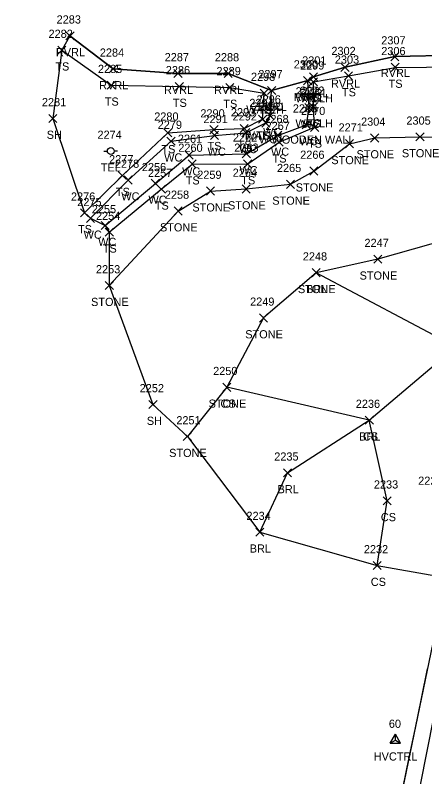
# Model space of a CAD drawing. Extents: x 1472022 to 1479249, y 777216 to 786527.
# Drawn here: x 1473450.2 to 1473550.5, y 779278.4 to 779464.9 of the extents above; entities that cross this region are included whole.
import ezdxf

# ---------------------------------------------------------------- set-up
doc = ezdxf.new("R2010")
doc.units = 0
for name, color, linetype in [('C_A', 7, 'Continuous'), ('C_I', 7, 'Continuous'), ('CPSM', 7, 'Continuous'), ('D_A', 7, 'Continuous'), ('D_C', 7, 'Continuous'), ('D_I', 7, 'Continuous'), ('D_TIC', 7, 'Continuous'), ('DHW', 7, 'Continuous'), ('L_A', 7, 'Continuous'), ('L_I', 7, 'Continuous'), ('L_TIC', 7, 'Continuous'), ('LABL', 7, 'Continuous'), ('LASF', 7, 'Continuous'), ('LAWE', 7, 'Continuous'), ('LELB', 7, 'Continuous'), ('LSOGP', 7, 'Continuous'), ('PET', 7, 'Continuous'), ('PSP', 7, 'Continuous'), ('U_A', 7, 'Continuous'), ('U_I', 7, 'Continuous'), ('UP', 7, 'Continuous')]:
    doc.layers.add(name, color=color, linetype=linetype)

msp = doc.modelspace()

# ---------------------------------------------------------------- linework, layer by layer
at = {"layer": 'CPSM'}
for p, q in [((1473542.08, 779286.66), (1473543.33, 779288.82)), ((1473544.58, 779286.66), (1473543.33, 779288.82)), ((1473543.33, 779287.38), (1473543.33, 779288.82)), ((1473542.08, 779286.66), (1473543.33, 779287.38)), ((1473542.08, 779286.66), (1473544.58, 779286.66)), ((1473543.33, 779287.38), (1473543.33, 779287.38)), ((1473543.33, 779287.38), (1473544.58, 779286.66))]:
    msp.add_line(p, q, dxfattribs=at)
at = {"layer": 'D_TIC'}
for points in [[(1473522.26, 779447.59), (1473524.26, 779449.59)], [(1473524.26, 779447.59), (1473522.26, 779449.59)], [(1473510.22, 779444.82), (1473512.22, 779446.82)], [(1473512.22, 779444.82), (1473510.22, 779446.82)], [(1473522.26, 779441.43), (1473524.26, 779443.43)], [(1473524.26, 779441.43), (1473522.26, 779443.43)], [(1473509.83, 779438.42), (1473511.83, 779440.42)], [(1473511.83, 779438.42), (1473509.83, 779440.42)]]:
    msp.add_lwpolyline(points, dxfattribs=at)
at = {"layer": 'DHW'}
for points in [[(1473523.26, 779442.43), (1473523.26, 779448.59)], [(1473510.83, 779439.42), (1473511.22, 779445.82)]]:
    msp.add_lwpolyline(points, dxfattribs=at)
at = {"layer": 'L_TIC'}
for points in [[(1473462.64, 779458.86), (1473464.64, 779460.86)], [(1473464.64, 779458.86), (1473462.64, 779460.86)], [(1473460.66, 779455.35), (1473462.66, 779457.35)], [(1473462.66, 779455.35), (1473460.66, 779457.35)], [(1473542.2, 779453.75), (1473544.2, 779455.75)], [(1473544.2, 779453.75), (1473542.2, 779455.75)], [(1473473.22, 779450.75), (1473475.22, 779452.75)], [(1473475.22, 779450.75), (1473473.22, 779452.75)], [(1473530, 779451.15), (1473532, 779453.15)], [(1473532, 779451.15), (1473530, 779453.15)], [(1473542.26, 779451.12), (1473544.26, 779453.12)], [(1473544.26, 779451.12), (1473542.26, 779453.12)], [(1473489.1, 779449.63), (1473491.1, 779451.63)], [(1473491.1, 779449.63), (1473489.1, 779451.63)], [(1473501.38, 779449.61), (1473503.38, 779451.61)], [(1473503.38, 779449.61), (1473501.38, 779451.61)], [(1473522.28, 779448.82), (1473524.28, 779450.82)], [(1473524.28, 779448.82), (1473522.28, 779450.82)], [(1473530.84, 779449.04), (1473532.84, 779451.04)], [(1473532.84, 779449.04), (1473530.84, 779451.04)], [(1473472.76, 779446.75), (1473474.76, 779448.75)], [(1473474.76, 779446.75), (1473472.76, 779448.75)], [(1473489.43, 779446.45), (1473491.43, 779448.45)], [(1473491.43, 779446.45), (1473489.43, 779448.45)], [(1473501.79, 779446.21), (1473503.79, 779448.21)], [(1473503.79, 779446.21), (1473501.79, 779448.21)], [(1473520.87, 779447.87), (1473522.87, 779449.87)], [(1473522.87, 779447.87), (1473520.87, 779449.87)], [(1473520.87, 779447.87), (1473522.87, 779449.87)], [(1473522.87, 779447.87), (1473520.87, 779449.87)], [(1473522.26, 779447.59), (1473524.26, 779449.59)], [(1473524.26, 779447.59), (1473522.26, 779449.59)], [(1473510.22, 779444.82), (1473512.22, 779446.82)], [(1473512.22, 779444.82), (1473510.22, 779446.82)], [(1473512.03, 779445.48), (1473514.03, 779447.48)], [(1473514.03, 779445.48), (1473512.03, 779447.48)], [(1473512.03, 779445.48), (1473514.03, 779447.48)], [(1473514.03, 779445.48), (1473512.03, 779447.48)], [(1473521.18, 779441.26), (1473523.18, 779443.26)], [(1473523.18, 779441.26), (1473521.18, 779443.26)], [(1473522.26, 779441.43), (1473524.26, 779443.43)], [(1473524.26, 779441.43), (1473522.26, 779443.43)], [(1473458.47, 779438.62), (1473460.47, 779440.62)], [(1473460.47, 779438.62), (1473458.47, 779440.62)], [(1473511.65, 779439.29), (1473513.65, 779441.29)], [(1473513.65, 779439.29), (1473511.65, 779441.29)], [(1473509.83, 779438.42), (1473511.83, 779440.42)], [(1473511.83, 779438.42), (1473509.83, 779440.42)], [(1473510.6, 779437.51), (1473512.6, 779439.51)], [(1473512.6, 779437.51), (1473510.6, 779439.51)], [(1473520.53, 779437.07), (1473522.53, 779439.07)], [(1473522.53, 779437.07), (1473520.53, 779439.07)], [(1473486.63, 779435.09), (1473488.63, 779437.09)], [(1473488.63, 779435.09), (1473486.63, 779437.09)], [(1473497.92, 779435.87), (1473499.92, 779437.87)], [(1473499.92, 779435.87), (1473497.92, 779437.87)], [(1473505.31, 779436.14), (1473507.31, 779438.14)], [(1473507.31, 779436.14), (1473505.31, 779438.14)], [(1473505.73, 779435.12), (1473507.73, 779437.12)], [(1473507.73, 779435.12), (1473505.73, 779437.12)], [(1473522.55, 779436.45), (1473524.55, 779438.45)], [(1473524.55, 779436.45), (1473522.55, 779438.45)], [(1473487.4, 779433.07), (1473489.4, 779435.07)], [(1473489.4, 779433.07), (1473487.4, 779435.07)], [(1473498.04, 779434.48), (1473500.04, 779436.48)], [(1473500.04, 779434.48), (1473498.04, 779436.48)], [(1473513.56, 779434.48), (1473515.56, 779436.48)], [(1473515.56, 779434.48), (1473513.56, 779436.48)], [(1473537.27, 779433.84), (1473539.27, 779435.84)], [(1473539.27, 779433.84), (1473537.27, 779435.84)], [(1473548.37, 779434.1), (1473550.37, 779436.1)], [(1473550.37, 779434.1), (1473548.37, 779436.1)], [(1473513.85, 779432.81), (1473515.85, 779434.81)], [(1473515.85, 779432.81), (1473513.85, 779434.81)], [(1473531.1, 779432.42), (1473533.1, 779434.42)], [(1473533.1, 779432.42), (1473531.1, 779434.42)], [(1473491.8, 779429.65), (1473493.8, 779431.65)], [(1473493.8, 779429.65), (1473491.8, 779431.65)], [(1473505.84, 779429.95), (1473507.84, 779431.95)], [(1473507.84, 779429.95), (1473505.84, 779431.95)], [(1473492.58, 779427.45), (1473494.58, 779429.45)], [(1473494.58, 779427.45), (1473492.58, 779429.45)], [(1473506.18, 779427.47), (1473508.18, 779429.47)], [(1473508.18, 779427.47), (1473506.18, 779429.47)], [(1473522.38, 779425.73), (1473524.38, 779427.73)], [(1473524.38, 779425.73), (1473522.38, 779427.73)], [(1473475.49, 779424.63), (1473477.49, 779426.63)], [(1473477.49, 779424.63), (1473475.49, 779426.63)], [(1473476.91, 779423.53), (1473478.91, 779425.53)], [(1473478.91, 779423.53), (1473476.91, 779425.53)], [(1473483.57, 779422.71), (1473485.57, 779424.71)], [(1473485.57, 779422.71), (1473483.57, 779424.71)], [(1473516.64, 779422.49), (1473518.64, 779424.49)], [(1473518.64, 779422.49), (1473516.64, 779424.49)], [(1473485.01, 779421.29), (1473487.01, 779423.29)], [(1473487.01, 779421.29), (1473485.01, 779423.29)], [(1473497.08, 779420.83), (1473499.08, 779422.83)], [(1473499.08, 779420.83), (1473497.08, 779422.83)], [(1473505.81, 779421.34), (1473507.81, 779423.34)], [(1473507.81, 779421.34), (1473505.81, 779423.34)], [(1473466.21, 779415.5), (1473468.21, 779417.5)], [(1473468.21, 779415.5), (1473466.21, 779417.5)], [(1473489.14, 779415.95), (1473491.14, 779417.95)], [(1473491.14, 779415.95), (1473489.14, 779417.95)], [(1473467.69, 779414.16), (1473469.69, 779416.16)], [(1473469.69, 779414.16), (1473467.69, 779416.16)], [(1473471.25, 779412.4), (1473473.25, 779414.4)], [(1473473.25, 779412.4), (1473471.25, 779414.4)], [(1473472.28, 779410.76), (1473474.28, 779412.76)], [(1473474.28, 779410.76), (1473472.28, 779412.76)], [(1473538.02, 779404.15), (1473540.02, 779406.15)], [(1473540.02, 779404.15), (1473538.02, 779406.15)], [(1473522.92, 779400.84), (1473524.92, 779402.84)], [(1473524.92, 779400.84), (1473522.92, 779402.84)], [(1473522.92, 779400.84), (1473524.92, 779402.84)], [(1473524.92, 779400.84), (1473522.92, 779402.84)], [(1473472.27, 779397.69), (1473474.27, 779399.69)], [(1473474.27, 779397.69), (1473472.27, 779399.69)], [(1473510.03, 779389.76), (1473512.03, 779391.76)], [(1473512.03, 779389.76), (1473510.03, 779391.76)], [(1473501.06, 779372.78), (1473503.06, 779374.78)], [(1473503.06, 779372.78), (1473501.06, 779374.78)], [(1473501.06, 779372.78), (1473503.06, 779374.78)], [(1473503.06, 779372.78), (1473501.06, 779374.78)], [(1473482.98, 779368.57), (1473484.98, 779370.57)], [(1473484.98, 779368.57), (1473482.98, 779370.57)], [(1473535.94, 779364.74), (1473537.94, 779366.74)], [(1473537.94, 779364.74), (1473535.94, 779366.74)], [(1473535.94, 779364.74), (1473537.94, 779366.74)], [(1473537.94, 779364.74), (1473535.94, 779366.74)], [(1473491.39, 779360.71), (1473493.39, 779362.71)], [(1473493.39, 779360.71), (1473491.39, 779362.71)], [(1473515.93, 779351.83), (1473517.93, 779353.83)], [(1473517.93, 779351.83), (1473515.93, 779353.83)], [(1473540.33, 779344.99), (1473542.33, 779346.99)], [(1473542.33, 779344.99), (1473540.33, 779346.99)], [(1473509.12, 779337.3), (1473511.12, 779339.3)], [(1473511.12, 779337.3), (1473509.12, 779339.3)], [(1473537.87, 779329.14), (1473539.87, 779331.14)], [(1473539.87, 779329.14), (1473537.87, 779331.14)]]:
    msp.add_lwpolyline(points, dxfattribs=at)
at = {"layer": 'LABL'}
msp.add_lwpolyline([(1473510.12, 779338.3), (1473516.93, 779352.83), (1473536.94, 779365.74), (1473558.14, 779383.69), (1473523.92, 779401.84)], dxfattribs=at)
at = {"layer": 'LASF'}
for points in [[(1473473.27, 779398.69), (1473490.14, 779416.95), (1473498.08, 779421.83), (1473506.81, 779422.34), (1473517.64, 779423.49), (1473523.38, 779426.73), (1473532.1, 779433.42), (1473538.27, 779434.84), (1473549.37, 779435.1), (1473559.65, 779434.83), (1473570.73, 779429.96), (1473585.71, 779426.72), (1473606.62, 779429.3), (1473628.1, 779421.5), (1473649.11, 779417.23), (1473669, 779413.11), (1473690.95, 779410.4), (1473712.68, 779400.49)], [(1473633.09, 779342.06), (1473637.36, 779354.76), (1473634.83, 779370.15), (1473634.39, 779386.13), (1473619.75, 779393.9), (1473604.91, 779393.47), (1473602.82, 779381.23), (1473597.4, 779362.46), (1473593.63, 779347.94), (1473579.62, 779350.93), (1473559.31, 779355.6), (1473561.08, 779365.73), (1473563.08, 779383.25), (1473565.84, 779398.86), (1473566.45, 779410.85), (1473556.37, 779410.02), (1473539.02, 779405.15), (1473523.92, 779401.84), (1473511.03, 779390.76), (1473502.06, 779373.78), (1473492.39, 779361.71)]]:
    msp.add_lwpolyline(points, dxfattribs=at)
at = {"layer": 'LAWE'}
for points in [[(1473463.64, 779459.86), (1473474.22, 779451.75), (1473490.1, 779450.63), (1473502.38, 779450.61), (1473513.03, 779446.48), (1473521.87, 779448.87), (1473523.28, 779449.82), (1473531, 779452.15), (1473543.2, 779454.75), (1473558.32, 779455.14), (1473569.13, 779457.8), (1473574.75, 779460.53), (1473588.89, 779462.56)], [(1473472.25, 779413.4), (1473484.57, 779423.71), (1473492.8, 779430.65), (1473506.84, 779430.95), (1473514.56, 779435.48), (1473521.53, 779438.07), (1473522.18, 779442.26), (1473521.87, 779448.87)], [(1473468.69, 779415.16), (1473477.91, 779424.53), (1473488.4, 779434.07), (1473499.04, 779435.48), (1473506.73, 779436.12), (1473511.6, 779438.51), (1473512.65, 779440.29), (1473513.03, 779446.48)]]:
    msp.add_lwpolyline(points, dxfattribs=at)
at = {"layer": 'LELB'}
for points in [[(1473523.26, 779448.59), (1473531.84, 779450.04), (1473543.26, 779452.12), (1473558.64, 779452.25), (1473569.37, 779453.99), (1473575.52, 779457.41), (1473586.54, 779458.61), (1473591.28, 779462.14)], [(1473461.66, 779456.35), (1473473.76, 779447.75), (1473490.43, 779447.45), (1473502.79, 779447.21), (1473511.22, 779445.82)], [(1473473.28, 779411.76), (1473486.01, 779422.29), (1473493.58, 779428.45), (1473507.18, 779428.47), (1473514.85, 779433.81), (1473523.55, 779437.45), (1473523.26, 779442.43)], [(1473467.21, 779416.5), (1473476.49, 779425.63), (1473487.63, 779436.09), (1473498.92, 779436.87), (1473506.31, 779437.14), (1473510.83, 779439.42)], [(1473538.87, 779330.14), (1473541.33, 779345.99), (1473536.94, 779365.74), (1473502.06, 779373.78)]]:
    msp.add_lwpolyline(points, dxfattribs=at)
at = {"layer": 'LSOGP'}
for points in [[(1473558.32, 779455.14), (1473543.2, 779454.75), (1473531, 779452.15), (1473523.28, 779449.82), (1473521.87, 779448.87), (1473513.03, 779446.48), (1473502.38, 779450.61), (1473490.1, 779450.63), (1473474.22, 779451.75), (1473463.64, 779459.86), (1473461.66, 779456.35), (1473459.47, 779439.62), (1473467.21, 779416.5), (1473468.69, 779415.16), (1473472.25, 779413.4), (1473473.28, 779411.76), (1473473.27, 779398.69), (1473483.98, 779369.57), (1473492.39, 779361.71), (1473510.12, 779338.3), (1473538.87, 779330.14), (1473553.21, 779327.61)], [(1473551.15, 779304.84), (1473549.65, 779297.61), (1473548.15, 779290.38), (1473546.65, 779283.15), (1473545.15, 779275.93)]]:
    msp.add_lwpolyline(points, dxfattribs=at)
at = {"layer": 'PET'}
msp.add_lwpolyline([(1473559.55, 779345.54), (1473562.13, 779344.85), (1473559.08, 779325.48), (1473547.78, 779268.19), (1473538.56, 779219.47), (1473529.75, 779172.07), (1473520.23, 779121.16), (1473510.25, 779071.91), (1473501.42, 779032.79), (1473487.97, 778980.7), (1473476.59, 778937.83), (1473460.83, 778885.95), (1473443.7, 778834.83), (1473427.04, 778789.1), (1473404.79, 778732.7), (1473383.99, 778685.53), (1473360.34, 778636.02), (1473337.25, 778590.82), (1473309.69, 778539.48), (1473284.14, 778496.13), (1473255.52, 778449.63), (1473221.14, 778399.57)], dxfattribs=at)
at = {"layer": 'PSP'}
msp.add_lwpolyline([(1473559.55, 779345.54), (1473556.55, 779328.39), (1473555.66, 779326.52), (1473543.65, 779268.7), (1473533.24, 779220.88), (1473523.59, 779172.64), (1473513.3, 779122.79), (1473502.95, 779073.62), (1473494.24, 779034.96), (1473482.21, 778985.43), (1473469.56, 778939.68), (1473453.46, 778887.37), (1473437.09, 778838.65), (1473419.76, 778792.02), (1473397.52, 778736.13), (1473377.14, 778688.43), (1473353.45, 778638.67), (1473330.09, 778593.76), (1473303, 778543.94), (1473277.25, 778499.77), (1473248.4, 778453.47), (1473214.72, 778403.13)], dxfattribs=at)
at = {"layer": 'UP'}
for p, q in [((1473471.98, 779431.62), (1473472.81, 779431.62)), ((1473473.64, 779431.63), (1473473.64, 779431.63)), ((1473475.31, 779431.63), (1473474.47, 779431.63)), ((1473474.47, 779431.63), (1473474.47, 779431.63)), ((1473475.31, 779431.63), (1473475.31, 779431.63))]:
    msp.add_line(p, q, dxfattribs=at)
msp.add_circle((1473473.64, 779431.63), 0.833, dxfattribs=at)

# ---------------------------------------------------------------- texts
at = {"layer": 'C_A'}
msp.add_text('HVCTRL', height=2, dxfattribs=at).set_placement((1473538.03, 779282.38))
at = {"layer": 'C_I'}
msp.add_text('60', height=2, dxfattribs=at).set_placement((1473541.73, 779290.38))
at = {"layer": 'D_A'}
for p in [(1473518.85, 779443.59), (1473506.81, 779440.82), (1473518.85, 779437.43), (1473506.42, 779434.42)]:
    msp.add_text('WALLH', height=2, dxfattribs=at).set_placement(p)
at = {"layer": 'D_C'}
msp.add_text('WOODEN WALL', height=2, dxfattribs=at).set_placement((1473513, 779433.43))
at = {"layer": 'D_I'}
for s, p in [('2299', (1473519.99, 779451.59)), ('2298', (1473507.96, 779448.82)), ('2272', (1473520, 779445.43)), ('2294', (1473507.57, 779442.42))]:
    msp.add_text(s, height=2, dxfattribs=at).set_placement(p)
at = {"layer": 'L_A'}
for s, p in [('RVRL', (1473460.21, 779454.86)), ('TS', (1473460.07, 779451.35)), ('RVRL', (1473539.77, 779449.75)), ('RVRL', (1473470.79, 779446.75)), ('RVRL', (1473527.56, 779447.15)), ('TS', (1473541.67, 779447.12)), ('RVRL', (1473486.66, 779445.63)), ('RVRL', (1473498.95, 779445.61)), ('RVRL', (1473519.84, 779444.82)), ('TS', (1473530.25, 779445.04)), ('TS', (1473472.17, 779442.75)), ('TS', (1473488.84, 779442.45)), ('RVRL', (1473518.44, 779443.87)), ('WC', (1473520.18, 779443.87)), ('TS', (1473521.67, 779443.59)), ('TS', (1473501.2, 779442.21)), ('TS', (1473509.63, 779440.82)), ('RVRL', (1473509.6, 779441.48)), ('WC', (1473511.34, 779441.48)), ('WC', (1473520.48, 779437.26)), ('TS', (1473521.67, 779437.43)), ('WC', (1473510.96, 779435.29)), ('SH', (1473457.96, 779434.62)), ('TS', (1473509.24, 779434.42)), ('WC', (1473509.91, 779433.51)), ('WC', (1473519.84, 779433.07)), ('TS', (1473486.04, 779431.09)), ('TS', (1473497.33, 779431.87)), ('TS', (1473504.71, 779432.14)), ('WC', (1473505.03, 779431.12)), ('TS', (1473521.96, 779432.45)), ('WC', (1473497.34, 779430.48)), ('WC', (1473512.86, 779430.48)), ('STONE', (1473533.81, 779429.84)), ('STONE', (1473544.92, 779430.1)), ('WC', (1473486.71, 779429.07)), ('TS', (1473513.26, 779428.81)), ('STONE', (1473527.64, 779428.42)), ('WC', (1473491.11, 779425.65)), ('WC', (1473505.15, 779425.95)), ('TS', (1473491.99, 779423.45)), ('TS', (1473505.59, 779423.47)), ('TS', (1473474.9, 779420.63)), ('STONE', (1473518.93, 779421.73)), ('WC', (1473476.22, 779419.53)), ('WC', (1473482.87, 779418.71)), ('STONE', (1473513.18, 779418.49)), ('TS', (1473484.42, 779417.29)), ('STONE', (1473493.62, 779416.83)), ('STONE', (1473502.35, 779417.34)), ('TS', (1473465.62, 779411.5)), ('STONE', (1473485.68, 779411.95)), ('WC', (1473466.99, 779410.16)), ('WC', (1473470.55, 779408.4)), ('TS', (1473471.68, 779406.76)), ('STONE', (1473534.57, 779400.15)), ('STONE', (1473519.47, 779396.84)), ('BRL', (1473521.47, 779396.84)), ('STONE', (1473468.81, 779393.69)), ('STONE', (1473506.57, 779385.76)), ('STONE', (1473497.6, 779368.78)), ('CS', (1473500.5, 779368.78)), ('SH', (1473482.47, 779364.57)), ('BRL', (1473534.48, 779360.74)), ('CS', (1473535.38, 779360.74)), ('STONE', (1473487.93, 779356.71)), ('BRL', (1473514.48, 779347.83)), ('CS', (1473539.77, 779340.99)), ('BRL', (1473507.66, 779333.3)), ('CS', (1473537.31, 779325.14))]:
    msp.add_text(s, height=2, dxfattribs=at).set_placement(p)
at = {"layer": 'L_I'}
for s, p in [('2283', (1473460.38, 779462.86)), ('2282', (1473458.4, 779459.35)), ('2307', (1473539.87, 779457.75)), ('2284', (1473470.96, 779454.75)), ('2287', (1473486.84, 779453.63)), ('2288', (1473499.12, 779453.61)), ('2302', (1473527.66, 779455.15)), ('2306', (1473539.87, 779455.12)), ('2300', (1473518.45, 779451.87)), ('2300', (1473518.45, 779451.87)), ('2299', (1473519.99, 779451.59)), ('2301', (1473520.5, 779452.82)), ('2303', (1473528.5, 779453.04)), ('2285', (1473470.5, 779450.75)), ('2286', (1473487.11, 779450.45)), ('2289', (1473499.52, 779450.21)), ('2298', (1473507.96, 779448.82)), ('2297', (1473509.77, 779449.48)), ('2297', (1473509.77, 779449.48)), ('2273', (1473518.92, 779445.26)), ('2272', (1473520, 779445.43)), ('2281', (1473456.78, 779442.62)), ('2294', (1473507.57, 779442.42)), ('2296', (1473509.33, 779443.29)), ('2295', (1473508.34, 779441.51)), ('2269', (1473518.22, 779441.07)), ('2270', (1473520.21, 779440.45)), ('2280', (1473484.28, 779439.09)), ('2290', (1473495.58, 779439.87)), ('2293', (1473503.05, 779440.14)), ('2292', (1473503.47, 779439.12)), ('2279', (1473485.13, 779437.07)), ('2291', (1473496.34, 779438.48)), ('2268', (1473511.25, 779438.48)), ('2267', (1473511.54, 779436.81)), ('2304', (1473534.93, 779437.84)), ('2305', (1473546.03, 779438.1)), ('2271', (1473529.41, 779436.42)), ('2261', (1473490.06, 779433.65)), ('2262', (1473503.54, 779433.95)), ('2260', (1473490.18, 779431.45)), ('2263', (1473503.87, 779431.47)), ('2266', (1473520.02, 779429.73)), ('2277', (1473473.23, 779428.63)), ('2278', (1473474.65, 779427.53)), ('2256', (1473481.25, 779426.71)), ('2265', (1473514.33, 779426.49)), ('2257', (1473482.75, 779425.29)), ('2259', (1473494.81, 779424.83)), ('2264', (1473503.5, 779425.34)), ('2258', (1473486.88, 779419.95)), ('2276', (1473463.89, 779419.5)), ('2275', (1473465.43, 779418.16)), ('2255', (1473468.99, 779416.4)), ('2254', (1473470.02, 779414.76)), ('2247', (1473535.76, 779408.15)), ('2248', (1473520.66, 779404.84)), ('2248', (1473520.66, 779404.84)), ('2253', (1473470.01, 779401.69)), ('2249', (1473507.76, 779393.76)), ('2250', (1473498.71, 779376.78)), ('2250', (1473498.71, 779376.78)), ('2252', (1473480.72, 779372.57)), ('2236', (1473533.63, 779368.74)), ('2236', (1473533.63, 779368.74)), ('2251', (1473489.69, 779364.71)), ('2235', (1473513.67, 779355.83)), ('2223', (1473548.91, 779349.9)), ('2233', (1473538.07, 779348.99)), ('2234', (1473506.86, 779341.3)), ('2232', (1473535.61, 779333.14))]:
    msp.add_text(s, height=2, dxfattribs=at).set_placement(p)
at = {"layer": 'U_A'}
msp.add_text('TEL', height=2, dxfattribs=at).set_placement((1473471.2, 779426.63))
at = {"layer": 'U_I'}
msp.add_text('2274', height=2, dxfattribs=at).set_placement((1473470.38, 779434.63))

doc.saveas('drawing.dxf')
